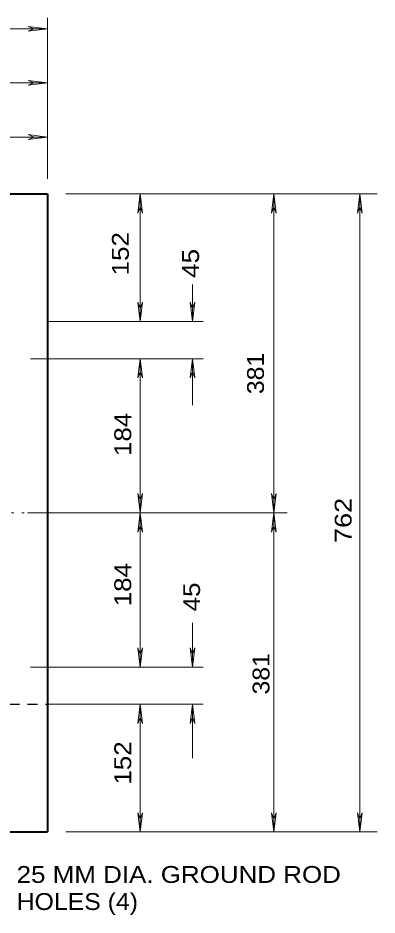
# Model space of a CAD drawing. Extents: x 312583 to 312854, y 144419 to 144597.
# Drawn here: x 312751.63 to 312767.81, y 144523.65 to 144564.08 of the extents above; entities that cross this region are included whole.
import ezdxf

# ---------------------------------------------------------------- set-up
doc = ezdxf.new("R2010")
doc.units = 0
doc.header["$LTSCALE"] = 0.3
doc.linetypes.add('DOTTED', pattern=[1.5, 0.3, -1.2])
doc.linetypes.add('SHORT_DASHED', pattern=[2.7, 1.5, -1.2])
doc.layers.add('1', color=7, linetype='Continuous', lineweight=25)
doc.layers.add('2', color=7, linetype='Continuous', lineweight=13)

msp = doc.modelspace()

# ---------------------------------------------------------------- linework, layer by layer
at = {"layer": '1', "lineweight": 40}
for p, q in [((312706.953, 144556.1486), (312752.953, 144556.1486)), ((312752.953, 144556.1486), (312752.953, 144527.3986)), ((312706.953, 144527.3986), (312752.953, 144527.3986))]:
    msp.add_line(p, q, dxfattribs=at)
at = {"layer": '1', "linetype": 'SHORT_DASHED'}
msp.add_line((312747.203, 144533.1486), (312752.953, 144533.1486), dxfattribs=at)
at = {"layer": '2'}
for p, q in [((312752.953, 144556.8233), (312752.953, 144564.0759)), ((312706.953, 144563.5853), (312752.953, 144563.5853)), ((312752.0867, 144563.6926), (312752.3627, 144563.5853)), ((312752.953, 144563.5853), (312752.0867, 144563.6926)), ((312752.0867, 144563.4779), (312752.3627, 144563.5853)), ((312752.953, 144563.5853), (312752.0867, 144563.4779)), ((312752.0867, 144561.2546), (312752.3627, 144561.1473)), ((312752.953, 144561.1473), (312752.0867, 144561.2546)), ((312752.0867, 144561.0399), (312752.3627, 144561.1473)), ((312752.953, 144561.1473), (312752.0867, 144561.0399)), ((312752.0867, 144558.8166), (312752.3627, 144558.7093)), ((312752.953, 144558.7093), (312752.0867, 144558.8166)), ((312752.0867, 144558.6019), (312752.3627, 144558.7093)), ((312752.953, 144558.7093), (312752.0867, 144558.6019)), ((312753.7887, 144556.1486), (312767.811, 144556.1486)), ((312757.139, 144556.1486), (312757.0317, 144555.2823)), ((312757.139, 144550.3986), (312757.139, 144556.1486)), ((312757.139, 144556.1486), (312757.2464, 144555.2823)), ((312763.1574, 144556.1486), (312763.05, 144555.2823)), ((312763.1574, 144556.1486), (312763.2647, 144555.2823)), ((312767.0367, 144556.1486), (312766.9294, 144555.2823)), ((312767.0367, 144527.3986), (312767.0367, 144556.1486)), ((312767.0367, 144556.1486), (312767.144, 144555.2823)), ((312757.0317, 144555.2823), (312757.139, 144555.5583)), ((312757.2464, 144555.2823), (312757.139, 144555.5583)), ((312763.05, 144555.2823), (312763.1574, 144555.5583)), ((312763.2647, 144555.2823), (312763.1574, 144555.5583)), ((312766.9294, 144555.2823), (312767.0367, 144555.5583)), ((312767.144, 144555.2823), (312767.0367, 144555.5583)), ((312759.4927, 144550.3986), (312759.4927, 144552.0623)), ((312757.0317, 144551.2649), (312757.139, 144550.9889)), ((312757.139, 144550.3986), (312757.0317, 144551.2649)), ((312757.2464, 144551.2649), (312757.139, 144550.9889)), ((312757.139, 144550.3986), (312757.2464, 144551.2649)), ((312759.3854, 144551.2649), (312759.4927, 144550.9889)), ((312759.4927, 144550.3986), (312759.3854, 144551.2649)), ((312759.6, 144551.2649), (312759.4927, 144550.9889)), ((312759.4927, 144550.3986), (312759.6, 144551.2649)), ((312752.953, 144550.3986), (312759.9757, 144550.3986)), ((312752.1864, 144548.7196), (312759.9757, 144548.7196)), ((312757.139, 144548.7196), (312757.0317, 144547.8533)), ((312757.139, 144548.7196), (312757.2464, 144547.8533)), ((312759.4927, 144548.7196), (312759.3854, 144547.8533)), ((312759.4927, 144546.6343), (312759.4927, 144548.7196)), ((312759.4927, 144548.7196), (312759.6, 144547.8533)), ((312757.0317, 144547.8533), (312757.139, 144548.1293)), ((312757.2464, 144547.8533), (312757.139, 144548.1293)), ((312759.3854, 144547.8533), (312759.4927, 144548.1293)), ((312759.6, 144547.8533), (312759.4927, 144548.1293)), ((312757.0317, 144542.6399), (312757.139, 144542.3639)), ((312757.139, 144541.7736), (312757.0317, 144542.6399)), ((312757.2464, 144542.6399), (312757.139, 144542.3639)), ((312757.139, 144541.7736), (312757.2464, 144542.6399)), ((312763.05, 144542.6399), (312763.1574, 144542.3639)), ((312763.1574, 144541.7736), (312763.05, 144542.6399)), ((312763.2647, 144542.6399), (312763.1574, 144542.3639)), ((312763.1574, 144541.7736), (312763.2647, 144542.6399)), ((312752.056, 144541.7736), (312763.763, 144541.7736)), ((312757.139, 144541.7736), (312757.0317, 144540.9073)), ((312757.139, 144541.7736), (312757.2464, 144540.9073)), ((312763.1574, 144541.7736), (312763.05, 144540.9073)), ((312763.1574, 144541.7736), (312763.2647, 144540.9073)), ((312757.0317, 144540.9073), (312757.139, 144541.1833)), ((312757.2464, 144540.9073), (312757.139, 144541.1833)), ((312763.05, 144540.9073), (312763.1574, 144541.1833)), ((312763.2647, 144540.9073), (312763.1574, 144541.1833)), ((312759.4927, 144534.8199), (312759.4927, 144536.8133)), ((312757.0317, 144535.6863), (312757.139, 144535.4103)), ((312757.139, 144534.8199), (312757.0317, 144535.6863)), ((312757.2464, 144535.6863), (312757.139, 144535.4103)), ((312757.139, 144534.8199), (312757.2464, 144535.6863)), ((312759.3854, 144535.6863), (312759.4927, 144535.4103)), ((312759.4927, 144534.8199), (312759.3854, 144535.6863)), ((312759.6, 144535.6863), (312759.4927, 144535.4103)), ((312759.4927, 144534.8199), (312759.6, 144535.6863)), ((312752.1864, 144534.8199), (312759.9757, 144534.8199)), ((312752.953, 144533.1486), (312759.9757, 144533.1486)), ((312757.139, 144533.1486), (312757.0317, 144532.2823)), ((312757.139, 144527.3986), (312757.139, 144533.1486)), ((312757.139, 144533.1486), (312757.2464, 144532.2823)), ((312759.4927, 144533.1486), (312759.3854, 144532.2823)), ((312759.4927, 144530.7183), (312759.4927, 144533.1486)), ((312759.4927, 144533.1486), (312759.6, 144532.2823)), ((312757.0317, 144532.2823), (312757.139, 144532.5583)), ((312757.2464, 144532.2823), (312757.139, 144532.5583)), ((312759.3854, 144532.2823), (312759.4927, 144532.5583)), ((312759.6, 144532.2823), (312759.4927, 144532.5583)), ((312757.0317, 144528.2649), (312757.139, 144527.9889)), ((312757.139, 144527.3986), (312757.0317, 144528.2649)), ((312757.2464, 144528.2649), (312757.139, 144527.9889)), ((312757.139, 144527.3986), (312757.2464, 144528.2649)), ((312763.05, 144528.2649), (312763.1574, 144527.9889)), ((312763.1574, 144527.3986), (312763.05, 144528.2649)), ((312763.2647, 144528.2649), (312763.1574, 144527.9889)), ((312763.1574, 144527.3986), (312763.2647, 144528.2649)), ((312766.9294, 144528.2649), (312767.0367, 144527.9889)), ((312767.0367, 144527.3986), (312766.9294, 144528.2649)), ((312767.144, 144528.2649), (312767.0367, 144527.9889)), ((312767.0367, 144527.3986), (312767.144, 144528.2649)), ((312753.7887, 144527.3986), (312767.811, 144527.3986))]:
    msp.add_line(p, q, dxfattribs=at)
at = {"layer": '2', "linetype": 'DOTTED'}
msp.add_line((312731.103, 144541.7736), (312752.056, 144541.7736), dxfattribs=at)
at = {"layer": '2'}
for points in [[(312706.953, 144561.1473), (312729.953, 144561.1473), (312752.953, 144561.1473)], [(312738.578, 144558.7093), (312742.4114, 144558.7093), (312747.203, 144558.7093), (312752.953, 144558.7093)], [(312763.1574, 144527.3986), (312763.1574, 144541.7736), (312763.1574, 144556.1486)], [(312757.139, 144534.8199), (312757.139, 144541.7736), (312757.139, 144548.7196)]]:
    msp.add_lwpolyline(points, dxfattribs=at)

# ---------------------------------------------------------------- texts
for s, width, p in [('152 ', 1.15, (312756.624, 144552.4772)), ('45 ', 1.15, (312759.7881, 144552.3651)), ('381 ', 1.1, (312762.7133, 144547.124)), ('184 ', 1.15, (312756.7303, 144544.3361)), ('762 ', 1.2, (312766.6635, 144540.4178)), ('184 ', 1.15, (312756.7303, 144537.5646)), ('45 ', 1.15, (312759.8333, 144537.3346)), ('381 ', 1.1, (312762.9613, 144533.5906)), ('152 ', 1.15, (312756.7304, 144529.5299))]:
    msp.add_text(s, height=0.76, rotation=90, dxfattribs=dict(at, width=width)).set_placement(p)
for s, width, p in [('25 MM DIA. GROUND ROD', 1.15, (312751.5692, 144525.1007)), ('HOLES (4)', 1.1, (312751.5692, 144523.8807))]:
    msp.add_text(s, height=0.76, dxfattribs=dict(at, width=width)).set_placement(p)

doc.saveas('drawing.dxf')
